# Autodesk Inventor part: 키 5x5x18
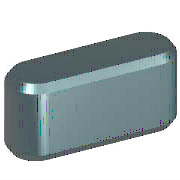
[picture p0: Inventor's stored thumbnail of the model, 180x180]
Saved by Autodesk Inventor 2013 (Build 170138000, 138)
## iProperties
Created: 2012-02
Part Number: 키 5x5x18
Material: 강철, 연강
Description: 키 및 해당 키홈
Document SubType Name: Modeling
Standard: KS B 1311
Designer: mduedu
Standards Organization: KS
Language: ko-KR
Size Designation: 5 x 5 x 18
Categories: <MemberInstance><Categories><Category DisplayName="샤프트 부품" InternalName="7f7aeb1f-a693-4053-b835-cee3144e0d98" Mnemonic="SHFT"><Category DisplayName="키" Interna
Density: 7.86 g/cm^3
Mass: 3.27476 g
Surface Area: 3.57848 cm^2
Volume: 0.416636 cm^3
IsCustomPart: 1
Author: mduedu
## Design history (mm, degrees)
workplane "Work Plane1"
workplane "Work Plane2"
sketch "스케치1"
  geometry: L1 (2.5, 2.5)-(15.5, 2.5); L2 (15.5, -2.5)-(2.5, -2.5); L3 (0, 9.4)-(0, -7.4) reference; L4 (-5, 0)-(30, 0) reference; L5 (18, 0)-(18, 7); A1 r 2.5 centre (2.5, 0) between (2.5, 2.5) and (2.5, -2.5); A2 r 2.5 centre (15.5, 0) between (15.5, -2.5) and (15.5, 2.5)
  constraints: 6 end point, 5 point on circle, 4 tangent, 3 point on line, 2 centre point, 1 horizontal, 1 parallel, 1 perpendicular
  dimensions: "d0" = 2.5 radius of A1 (= 0.5 x PB); "d13" = 2.5 radius of A2 (= 0.5 x PB); "d14" = 18 distance between parallel lines of L5 L3 (= NLG)
extrude "본체1" new body sketch "스케치1" taper "d3" = 0 deg; stored distance "d4" = 10
workplane "Work Plane3"
body "Solid1"
chamfer "모따기1" distance "d8" = 0.4 (= PHH); stored, may be unused: second distance "d9" = 0.4 (= PHH), angle "d15" = 45 deg
other parameters: "d1" = -3 (= -PNT), "d2" = 2 (= PH - PNT), "NLG" = 18 [user parameter; used in 3 equation terms], "PB" = 5 [user parameter; used in 2 equation terms], "PNT" = 3 [user parameter; used in 2 equation terms], "PH" = 5 [user parameter; used in 1 equation term], "PHH" = 0.4 [user parameter; used in 2 equation terms], "d10" = 0, "d16" = 0, "d17" = 0, "d18" = 0, "WDMIN" = 12 [user parameter], "PLB2" = 18 (= NLG) [user parameter], "WDMAX" = 17 [user parameter], "PLB1" = 18 (= NLG) [user parameter], "RR" = 0.16 [user parameter], "PUEB" = 2.3 [user parameter]
